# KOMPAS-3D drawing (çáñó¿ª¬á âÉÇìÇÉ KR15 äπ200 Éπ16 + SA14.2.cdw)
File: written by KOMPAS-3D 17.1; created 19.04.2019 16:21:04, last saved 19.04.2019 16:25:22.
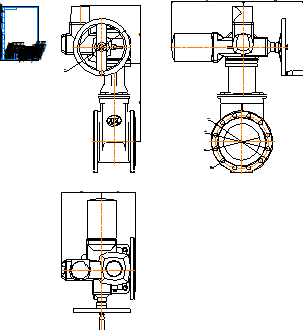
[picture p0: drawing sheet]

Sheet 1: A4, portrait

Title block, sheet 1: name: Задвижка ГРАНАР KR15 Ду200 Ру16 + SA14.2; material: Внимание! Данный продукт является объектом авторского права ООО «Торговый Дом АДЛ». / Запрещается изменение, копирование, распространение / (в том числе путем копирования на другие сайты и ресурсы в Интернете) / или любое иное использование информации и объектов без предварительного / согласия правообладателя (ООО «Торговый Дом АДЛ»).; mass: 220,79; sheets: 1; organisation: ООО "Торговый дом АДЛ"; sheet format: A4

Views: Вид 1, Проекционный вид 2, Проекционный вид 3
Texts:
  user
Dimensions and other numbers on the sheet: 340; 295; 430; 316; 315; 200; 22; 12 Отв.; 396; 328,3; 218,8; 182; 1:1; 1; 220,79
